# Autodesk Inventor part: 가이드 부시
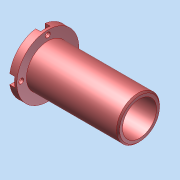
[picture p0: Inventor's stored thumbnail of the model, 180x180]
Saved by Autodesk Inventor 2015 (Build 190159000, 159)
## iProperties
Created: 2026-09
Part Number: 가이드 부시
Material: 일반
Document SubType Name: Modeling
Designer: SCD-A06
Density: 1 g/cm^3
Appearance: 기본값
Author: SCD-A06
Author: jhkim
Creation Date: 2026-08-27
Sending System: Autodesk Inventor 2027
Preprocessor: ST-DEVELOPER v20.1
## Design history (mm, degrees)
node "가이드 부시1"
node "솔리드1"
node "기준1"
